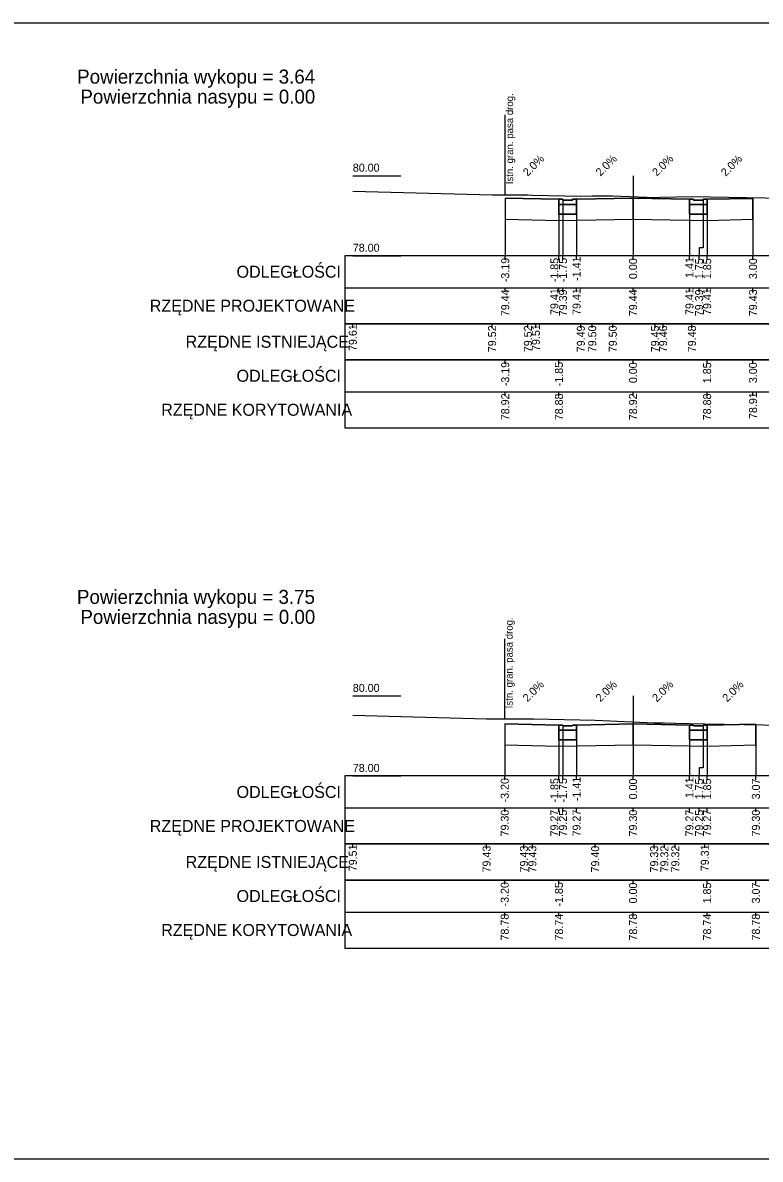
# Model space of a CAD drawing. Extents: x 7492871 to 7493499, y 5802964 to 5802992.
# Drawn here: x 7492955.98 to 7492974.4, y 5802963.88 to 5802992.28 of the extents above; entities that cross this region are included whole.
import ezdxf

# ---------------------------------------------------------------- set-up
doc = ezdxf.new("R2010")
doc.units = 0
for name, color, linetype in [('_wydruk', 7, 'Continuous'), ('d_pop_nasyp_opis', 7, 'Continuous'), ('d_pop_wykop_opis', 7, 'Continuous'), ('opisy_ramki_pop', 7, 'Continuous'), ('pop_comp_kostka', 7, 'Continuous'), ('pop_comp_lawa', 7, 'Continuous'), ('pop_comp_scieralna', 7, 'Continuous'), ('pop_granica_istn', 7, 'Continuous'), ('pop_opis', 7, 'Continuous'), ('pop_os', 7, 'Continuous'), ('pop_teren', 7, 'Continuous')]:
    doc.layers.add(name, color=color, linetype=linetype)

msp = doc.modelspace()

# ---------------------------------------------------------------- linework, layer by layer
for points in [[(7492968.028, 5802987.894), (7492969.37, 5802987.868), (7492969.47, 5802987.868), (7492969.471, 5802987.848), (7492969.71, 5802987.848), (7492969.711, 5802987.868), (7492969.811, 5802987.868), (7492971.221, 5802987.896), (7492972.631, 5802987.868), (7492972.731, 5802987.868), (7492972.732, 5802987.848), (7492972.971, 5802987.848), (7492972.972, 5802987.868), (7492973.072, 5802987.868), (7492974.218, 5802987.891)], [(7492968.016, 5802974.758), (7492969.37, 5802974.73), (7492969.47, 5802974.73), (7492969.471, 5802974.71), (7492969.71, 5802974.71), (7492969.711, 5802974.73), (7492969.811, 5802974.73), (7492971.221, 5802974.759), (7492972.631, 5802974.73), (7492972.731, 5802974.73), (7492972.732, 5802974.71), (7492972.971, 5802974.71), (7492972.972, 5802974.73), (7492973.072, 5802974.73), (7492974.29, 5802974.755)]]:
    msp.add_lwpolyline(points)
at = {"layer": '_wydruk'}
msp.add_lwpolyline([(7492871.369, 5802992.281), (7493499.283, 5802992.281), (7493499.283, 5802963.881), (7492871.369, 5802963.881)], close=True, dxfattribs=at)
at = {"layer": 'opisy_ramki_pop'}
for points in [[(7492968.028, 5802987.374), (7492968.028, 5802986.659), (7492968.028, 5802986.659), (7492968.028, 5802986.459)], [(7492969.37, 5802987.339), (7492969.37, 5802986.659), (7492969.37, 5802986.659), (7492969.37, 5802986.459)], [(7492971.221, 5802987.376), (7492971.221, 5802986.659), (7492971.221, 5802986.659), (7492971.221, 5802986.459)], [(7492973.072, 5802987.339), (7492973.072, 5802986.659), (7492973.072, 5802986.659), (7492973.072, 5802986.459)], [(7492974.218, 5802987.37), (7492974.218, 5802986.659), (7492974.218, 5802986.659), (7492974.218, 5802986.459)], [(7492968.016, 5802974.237), (7492968.016, 5802973.659), (7492968.016, 5802973.659), (7492968.016, 5802973.459)], [(7492969.37, 5802974.202), (7492969.37, 5802973.659), (7492969.37, 5802973.659), (7492969.37, 5802973.459)], [(7492971.221, 5802974.239), (7492971.221, 5802973.659), (7492971.221, 5802973.659), (7492971.221, 5802973.459)], [(7492973.072, 5802974.202), (7492973.072, 5802973.659), (7492973.072, 5802973.659), (7492973.072, 5802973.459)], [(7492974.29, 5802974.235), (7492974.29, 5802973.659), (7492974.29, 5802973.659), (7492974.29, 5802973.459)]]:
    msp.add_lwpolyline(points, dxfattribs=at)
at = {"layer": 'pop_comp_kostka'}
for p, q in [((7492969.47, 5802987.868), (7492969.37, 5802987.868)), ((7492969.37, 5802987.868), (7492969.37, 5802987.738)), ((7492969.37, 5802987.738), (7492969.811, 5802987.738)), ((7492969.471, 5802987.848), (7492969.47, 5802987.868)), ((7492969.71, 5802987.848), (7492969.471, 5802987.848)), ((7492969.711, 5802987.868), (7492969.71, 5802987.848)), ((7492969.811, 5802987.868), (7492969.711, 5802987.868)), ((7492969.811, 5802987.738), (7492969.811, 5802987.868)), ((7492972.731, 5802987.868), (7492972.631, 5802987.868)), ((7492972.631, 5802987.868), (7492972.631, 5802987.738)), ((7492972.631, 5802987.738), (7492973.072, 5802987.738)), ((7492972.732, 5802987.848), (7492972.731, 5802987.868)), ((7492972.971, 5802987.848), (7492972.732, 5802987.848)), ((7492972.972, 5802987.868), (7492972.971, 5802987.848)), ((7492973.072, 5802987.868), (7492972.972, 5802987.868)), ((7492973.072, 5802987.738), (7492973.072, 5802987.868)), ((7492969.47, 5802974.73), (7492969.37, 5802974.73)), ((7492969.37, 5802974.73), (7492969.37, 5802974.6)), ((7492969.37, 5802974.6), (7492969.811, 5802974.6)), ((7492969.471, 5802974.71), (7492969.47, 5802974.73)), ((7492969.71, 5802974.71), (7492969.471, 5802974.71)), ((7492969.711, 5802974.73), (7492969.71, 5802974.71)), ((7492969.811, 5802974.73), (7492969.711, 5802974.73)), ((7492969.811, 5802974.6), (7492969.811, 5802974.73)), ((7492972.731, 5802974.73), (7492972.631, 5802974.73)), ((7492972.631, 5802974.73), (7492972.631, 5802974.6)), ((7492972.631, 5802974.6), (7492973.072, 5802974.6)), ((7492972.732, 5802974.71), (7492972.731, 5802974.73)), ((7492972.971, 5802974.71), (7492972.732, 5802974.71)), ((7492972.972, 5802974.73), (7492972.971, 5802974.71)), ((7492973.072, 5802974.73), (7492972.972, 5802974.73)), ((7492973.072, 5802974.6), (7492973.072, 5802974.73))]:
    msp.add_line(p, q, dxfattribs=at)
at = {"layer": 'pop_comp_lawa'}
for p, q in [((7492969.811, 5802987.738), (7492969.37, 5802987.738)), ((7492969.37, 5802987.738), (7492969.37, 5802987.497)), ((7492969.811, 5802987.497), (7492969.811, 5802987.738)), ((7492973.072, 5802987.738), (7492972.631, 5802987.738)), ((7492972.631, 5802987.738), (7492972.631, 5802987.497)), ((7492973.072, 5802987.497), (7492973.072, 5802987.738)), ((7492969.37, 5802987.497), (7492969.811, 5802987.497)), ((7492972.631, 5802987.497), (7492973.072, 5802987.497)), ((7492969.811, 5802974.6), (7492969.37, 5802974.6)), ((7492969.37, 5802974.6), (7492969.37, 5802974.36)), ((7492969.811, 5802974.36), (7492969.811, 5802974.6)), ((7492973.072, 5802974.6), (7492972.631, 5802974.6)), ((7492972.631, 5802974.6), (7492972.631, 5802974.36)), ((7492973.072, 5802974.36), (7492973.072, 5802974.6)), ((7492969.37, 5802974.36), (7492969.811, 5802974.36)), ((7492972.631, 5802974.36), (7492973.072, 5802974.36))]:
    msp.add_line(p, q, dxfattribs=at)
at = {"layer": 'pop_comp_scieralna'}
for p, q in [((7492969.37, 5802987.868), (7492968.028, 5802987.894)), ((7492968.028, 5802987.894), (7492968.028, 5802987.374)), ((7492969.37, 5802987.497), (7492969.37, 5802987.868)), ((7492971.221, 5802987.896), (7492969.811, 5802987.868)), ((7492969.811, 5802987.868), (7492969.811, 5802987.497)), ((7492971.221, 5802987.376), (7492971.221, 5802987.896)), ((7492972.631, 5802987.868), (7492971.221, 5802987.896)), ((7492971.221, 5802987.896), (7492971.221, 5802987.376)), ((7492972.631, 5802987.497), (7492972.631, 5802987.868)), ((7492974.218, 5802987.891), (7492973.072, 5802987.868)), ((7492973.072, 5802987.868), (7492973.072, 5802987.497)), ((7492974.218, 5802987.37), (7492974.218, 5802987.891)), ((7492968.028, 5802987.374), (7492969.37, 5802987.339)), ((7492969.811, 5802987.497), (7492969.37, 5802987.497)), ((7492969.37, 5802987.339), (7492971.221, 5802987.376)), ((7492971.221, 5802987.376), (7492973.072, 5802987.339)), ((7492973.072, 5802987.497), (7492972.631, 5802987.497)), ((7492973.072, 5802987.339), (7492974.218, 5802987.37)), ((7492969.37, 5802974.73), (7492968.016, 5802974.758)), ((7492968.016, 5802974.758), (7492968.016, 5802974.237)), ((7492969.37, 5802974.36), (7492969.37, 5802974.73)), ((7492971.221, 5802974.759), (7492969.811, 5802974.73)), ((7492969.811, 5802974.73), (7492969.811, 5802974.36)), ((7492971.221, 5802974.239), (7492971.221, 5802974.759)), ((7492972.631, 5802974.73), (7492971.221, 5802974.759)), ((7492971.221, 5802974.759), (7492971.221, 5802974.239)), ((7492972.631, 5802974.36), (7492972.631, 5802974.73)), ((7492974.29, 5802974.755), (7492973.072, 5802974.73)), ((7492973.072, 5802974.73), (7492973.072, 5802974.36)), ((7492974.29, 5802974.235), (7492974.29, 5802974.755)), ((7492969.811, 5802974.36), (7492969.37, 5802974.36)), ((7492973.072, 5802974.36), (7492972.631, 5802974.36)), ((7492968.016, 5802974.237), (7492969.37, 5802974.202)), ((7492969.37, 5802974.202), (7492971.221, 5802974.239)), ((7492971.221, 5802974.239), (7492973.072, 5802974.202)), ((7492973.072, 5802974.202), (7492974.29, 5802974.235))]:
    msp.add_line(p, q, dxfattribs=at)
at = {"layer": 'pop_granica_istn'}
for p, q in [((7492968.028, 5802988.482), (7492968.028, 5802989.982)), ((7492968.028, 5802987.982), (7492968.028, 5802988.482)), ((7492968.016, 5802975.388), (7492968.016, 5802976.888)), ((7492968.016, 5802974.888), (7492968.016, 5802975.388))]:
    msp.add_line(p, q, dxfattribs=at)
at = {"layer": 'pop_opis'}
for p, q in [((7492964.221, 5802988.459), (7492965.421, 5802988.459)), ((7492964.021, 5802986.459), (7492964.021, 5802984.759)), ((7492964.021, 5802986.459), (7492964.021, 5802984.759)), ((7492964.021, 5802986.459), (7492964.021, 5802984.759)), ((7492964.021, 5802986.459), (7492964.021, 5802984.759)), ((7492964.221, 5802986.459), (7492965.421, 5802986.459)), ((7492968.028, 5802986.359), (7492968.028, 5802986.459)), ((7492969.37, 5802986.359), (7492969.37, 5802986.459)), ((7492969.471, 5802986.359), (7492969.471, 5802986.459)), ((7492969.811, 5802986.359), (7492969.811, 5802986.459)), ((7492971.221, 5802986.359), (7492971.221, 5802986.459)), ((7492972.631, 5802986.359), (7492972.631, 5802986.459)), ((7492972.872, 5802986.359), (7492972.872, 5802986.459)), ((7492973.072, 5802986.359), (7492973.072, 5802986.459)), ((7492974.218, 5802986.359), (7492974.218, 5802986.459)), ((7492964.021, 5802985.659), (7492978.421, 5802985.659)), ((7492964.021, 5802985.659), (7492978.421, 5802985.659)), ((7492964.021, 5802985.659), (7492978.421, 5802985.659)), ((7492964.021, 5802985.659), (7492978.421, 5802985.659)), ((7492968.028, 5802985.559), (7492968.028, 5802985.659)), ((7492969.37, 5802985.559), (7492969.37, 5802985.659)), ((7492969.471, 5802985.559), (7492969.471, 5802985.659)), ((7492969.811, 5802985.559), (7492969.811, 5802985.659)), ((7492971.221, 5802985.559), (7492971.221, 5802985.659)), ((7492972.631, 5802985.559), (7492972.631, 5802985.659)), ((7492972.872, 5802985.559), (7492972.872, 5802985.659)), ((7492973.072, 5802985.559), (7492973.072, 5802985.659)), ((7492974.218, 5802985.559), (7492974.218, 5802985.659)), ((7492964.021, 5802984.759), (7492964.021, 5802983.859)), ((7492964.221, 5802984.659), (7492964.221, 5802984.759)), ((7492967.7, 5802984.659), (7492967.7, 5802984.759)), ((7492968.594, 5802984.659), (7492968.594, 5802984.759)), ((7492968.794, 5802984.659), (7492968.794, 5802984.759)), ((7492969.917, 5802984.659), (7492969.917, 5802984.759)), ((7492970.203, 5802984.659), (7492970.203, 5802984.759)), ((7492970.715, 5802984.659), (7492970.715, 5802984.759)), ((7492971.771, 5802984.659), (7492971.771, 5802984.759)), ((7492971.971, 5802984.659), (7492971.971, 5802984.759)), ((7492972.692, 5802984.659), (7492972.692, 5802984.759)), ((7492964.021, 5802983.859), (7492964.021, 5802982.159)), ((7492968.028, 5802983.759), (7492968.028, 5802983.859)), ((7492969.37, 5802983.759), (7492969.37, 5802983.859)), ((7492971.221, 5802983.759), (7492971.221, 5802983.859)), ((7492973.072, 5802983.759), (7492973.072, 5802983.859)), ((7492974.218, 5802983.759), (7492974.218, 5802983.859)), ((7492964.021, 5802983.059), (7492978.421, 5802983.059)), ((7492968.028, 5802982.959), (7492968.028, 5802983.059)), ((7492969.37, 5802982.959), (7492969.37, 5802983.059)), ((7492971.221, 5802982.959), (7492971.221, 5802983.059)), ((7492973.072, 5802982.959), (7492973.072, 5802983.059)), ((7492974.218, 5802982.959), (7492974.218, 5802983.059)), ((7492964.221, 5802975.459), (7492965.421, 5802975.459)), ((7492964.021, 5802973.459), (7492964.021, 5802971.759)), ((7492964.021, 5802973.459), (7492964.021, 5802971.759)), ((7492964.021, 5802973.459), (7492964.021, 5802971.759)), ((7492964.021, 5802973.459), (7492964.021, 5802971.759)), ((7492964.221, 5802973.459), (7492965.421, 5802973.459)), ((7492968.016, 5802973.359), (7492968.016, 5802973.459)), ((7492969.37, 5802973.359), (7492969.37, 5802973.459)), ((7492969.471, 5802973.359), (7492969.471, 5802973.459)), ((7492969.811, 5802973.359), (7492969.811, 5802973.459)), ((7492971.221, 5802973.359), (7492971.221, 5802973.459)), ((7492972.631, 5802973.359), (7492972.631, 5802973.459)), ((7492972.872, 5802973.359), (7492972.872, 5802973.459)), ((7492973.072, 5802973.359), (7492973.072, 5802973.459)), ((7492974.29, 5802973.359), (7492974.29, 5802973.459)), ((7492964.021, 5802972.659), (7492978.421, 5802972.659)), ((7492964.021, 5802972.659), (7492978.421, 5802972.659)), ((7492964.021, 5802972.659), (7492978.421, 5802972.659)), ((7492964.021, 5802972.659), (7492978.421, 5802972.659)), ((7492968.016, 5802972.559), (7492968.016, 5802972.659)), ((7492969.37, 5802972.559), (7492969.37, 5802972.659)), ((7492969.471, 5802972.559), (7492969.471, 5802972.659)), ((7492969.811, 5802972.559), (7492969.811, 5802972.659)), ((7492971.221, 5802972.559), (7492971.221, 5802972.659)), ((7492972.631, 5802972.559), (7492972.631, 5802972.659)), ((7492972.872, 5802972.559), (7492972.872, 5802972.659)), ((7492973.072, 5802972.559), (7492973.072, 5802972.659)), ((7492974.29, 5802972.559), (7492974.29, 5802972.659)), ((7492964.021, 5802971.759), (7492964.021, 5802970.859)), ((7492964.221, 5802971.659), (7492964.221, 5802971.759)), ((7492967.563, 5802971.659), (7492967.563, 5802971.759)), ((7492968.496, 5802971.659), (7492968.496, 5802971.759)), ((7492968.706, 5802971.659), (7492968.706, 5802971.759)), ((7492970.275, 5802971.659), (7492970.275, 5802971.759)), ((7492971.749, 5802971.659), (7492971.749, 5802971.759)), ((7492972.004, 5802971.659), (7492972.004, 5802971.759)), ((7492972.277, 5802971.659), (7492972.277, 5802971.759)), ((7492973.013, 5802971.659), (7492973.013, 5802971.759)), ((7492964.021, 5802970.859), (7492964.021, 5802969.159)), ((7492968.016, 5802970.759), (7492968.016, 5802970.859)), ((7492969.37, 5802970.759), (7492969.37, 5802970.859)), ((7492971.221, 5802970.759), (7492971.221, 5802970.859)), ((7492973.072, 5802970.759), (7492973.072, 5802970.859)), ((7492974.29, 5802970.759), (7492974.29, 5802970.859)), ((7492964.021, 5802970.059), (7492978.421, 5802970.059)), ((7492968.016, 5802969.959), (7492968.016, 5802970.059)), ((7492969.37, 5802969.959), (7492969.37, 5802970.059)), ((7492971.221, 5802969.959), (7492971.221, 5802970.059)), ((7492973.072, 5802969.959), (7492973.072, 5802970.059)), ((7492974.29, 5802969.959), (7492974.29, 5802970.059))]:
    msp.add_line(p, q, dxfattribs=at)
for points in [[(7492968.028, 5802987.894), (7492968.028, 5802986.659), (7492968.028, 5802986.659), (7492968.028, 5802986.459)], [(7492969.37, 5802987.868), (7492969.37, 5802986.659), (7492969.37, 5802986.659), (7492969.37, 5802986.459)], [(7492969.471, 5802987.848), (7492969.471, 5802986.659), (7492969.471, 5802986.659), (7492969.471, 5802986.459)], [(7492969.811, 5802987.868), (7492969.811, 5802986.659), (7492969.811, 5802986.659), (7492969.811, 5802986.459)], [(7492971.221, 5802987.896), (7492971.221, 5802986.659), (7492971.221, 5802986.659), (7492971.221, 5802986.459)], [(7492972.631, 5802987.868), (7492972.631, 5802986.659), (7492972.631, 5802986.659), (7492972.631, 5802986.459)], [(7492972.971, 5802987.848), (7492972.971, 5802986.659), (7492972.872, 5802986.659), (7492972.872, 5802986.459)], [(7492973.072, 5802987.868), (7492973.072, 5802986.659), (7492973.072, 5802986.659), (7492973.072, 5802986.459)], [(7492974.218, 5802987.891), (7492974.218, 5802986.659), (7492974.218, 5802986.659), (7492974.218, 5802986.459)], [(7492968.016, 5802974.758), (7492968.016, 5802973.659), (7492968.016, 5802973.659), (7492968.016, 5802973.459)], [(7492969.37, 5802974.73), (7492969.37, 5802973.659), (7492969.37, 5802973.659), (7492969.37, 5802973.459)], [(7492969.471, 5802974.71), (7492969.471, 5802973.659), (7492969.471, 5802973.659), (7492969.471, 5802973.459)], [(7492969.811, 5802974.73), (7492969.811, 5802973.659), (7492969.811, 5802973.659), (7492969.811, 5802973.459)], [(7492971.221, 5802974.759), (7492971.221, 5802973.659), (7492971.221, 5802973.659), (7492971.221, 5802973.459)], [(7492972.631, 5802974.73), (7492972.631, 5802973.659), (7492972.631, 5802973.659), (7492972.631, 5802973.459)], [(7492972.971, 5802974.71), (7492972.971, 5802973.659), (7492972.872, 5802973.659), (7492972.872, 5802973.459)], [(7492973.072, 5802974.73), (7492973.072, 5802973.659), (7492973.072, 5802973.659), (7492973.072, 5802973.459)], [(7492974.29, 5802974.755), (7492974.29, 5802973.659), (7492974.29, 5802973.659), (7492974.29, 5802973.459)]]:
    msp.add_lwpolyline(points, dxfattribs=at)
for points in [[(7492964.021, 5802986.459), (7492964.021, 5802984.759), (7492978.421, 5802984.759), (7492978.421, 5802986.459)], [(7492964.021, 5802986.459), (7492964.021, 5802984.759), (7492978.421, 5802984.759), (7492978.421, 5802986.459)], [(7492964.021, 5802986.459), (7492964.021, 5802984.759), (7492978.421, 5802984.759), (7492978.421, 5802986.459)], [(7492964.021, 5802986.459), (7492964.021, 5802984.759), (7492978.421, 5802984.759), (7492978.421, 5802986.459)], [(7492964.021, 5802984.759), (7492964.021, 5802983.859), (7492978.421, 5802983.859), (7492978.421, 5802984.759)], [(7492964.021, 5802983.859), (7492964.021, 5802982.159), (7492978.421, 5802982.159), (7492978.421, 5802983.859)], [(7492964.021, 5802973.459), (7492964.021, 5802971.759), (7492978.421, 5802971.759), (7492978.421, 5802973.459)], [(7492964.021, 5802973.459), (7492964.021, 5802971.759), (7492978.421, 5802971.759), (7492978.421, 5802973.459)], [(7492964.021, 5802973.459), (7492964.021, 5802971.759), (7492978.421, 5802971.759), (7492978.421, 5802973.459)], [(7492964.021, 5802973.459), (7492964.021, 5802971.759), (7492978.421, 5802971.759), (7492978.421, 5802973.459)], [(7492964.021, 5802971.759), (7492964.021, 5802970.859), (7492978.421, 5802970.859), (7492978.421, 5802971.759)], [(7492964.021, 5802970.859), (7492964.021, 5802969.159), (7492978.421, 5802969.159), (7492978.421, 5802970.859)]]:
    msp.add_lwpolyline(points, close=True, dxfattribs=at)
at = {"layer": 'pop_os'}
for p, q in [((7492971.221, 5802988.459), (7492971.221, 5802986.459)), ((7492971.221, 5802975.459), (7492971.221, 5802973.459))]:
    msp.add_line(p, q, dxfattribs=at)
at = {"layer": 'pop_teren'}
for points in [[(7492964.221, 5802988.072), (7492967.7, 5802987.983), (7492968.594, 5802987.983), (7492968.708, 5802987.972), (7492969.917, 5802987.949), (7492970.203, 5802987.954), (7492970.715, 5802987.956), (7492971.771, 5802987.91), (7492971.895, 5802987.919), (7492972.692, 5802987.942), (7492976.366, 5802987.876), (7492978.221, 5802987.859)], [(7492964.221, 5802974.974), (7492967.563, 5802974.888), (7492968.496, 5802974.888), (7492968.706, 5802974.888), (7492968.736, 5802974.887), (7492970.275, 5802974.854), (7492971.749, 5802974.79), (7492972.004, 5802974.783), (7492972.277, 5802974.776), (7492973.013, 5802974.765), (7492977.401, 5802974.685), (7492978.221, 5802974.678)]]:
    msp.add_lwpolyline(points, dxfattribs=at)

# ---------------------------------------------------------------- texts
at = {"layer": 'd_pop_nasyp_opis'}
for p in [(7492957.416, 5802990.259), (7492957.416, 5802977.259)]:
    msp.add_text('Powierzchnia nasypu = 0.00', height=0.35, dxfattribs=at).set_placement(p)
at = {"layer": 'd_pop_wykop_opis'}
for s, p in [('Powierzchnia wykopu = 3.64', (7492957.335, 5802990.759)), ('Powierzchnia wykopu = 3.75', (7492957.33, 5802977.759))]:
    msp.add_text(s, height=0.35, dxfattribs=at).set_placement(p)
at = {"layer": 'pop_granica_istn'}
for p in [(7492968.226, 5802988.244), (7492968.214, 5802975.149)]:
    msp.add_text('Istn. gran. pasa drog.', height=0.18, rotation=90, dxfattribs=at).set_placement(p)
at = {"layer": 'pop_opis'}
for s, height, p in [('80.00', 0.2, (7492964.221, 5802988.559)), ('78.00', 0.2, (7492964.221, 5802986.559)), ('ODLEGŁOŚCI', 0.3, (7492961.317, 5802985.909)), ('ODLEGŁOŚCI', 0.3, (7492961.317, 5802985.909)), ('ODLEGŁOŚCI', 0.3, (7492961.317, 5802985.909)), ('ODLEGŁOŚCI', 0.3, (7492961.317, 5802985.909)), ('RZĘDNE PROJEKTOWANE', 0.3, (7492959.149, 5802985.059)), ('RZĘDNE PROJEKTOWANE', 0.3, (7492959.149, 5802985.059)), ('RZĘDNE PROJEKTOWANE', 0.3, (7492959.149, 5802985.059)), ('RZĘDNE PROJEKTOWANE', 0.3, (7492959.149, 5802985.059)), ('RZĘDNE ISTNIEJĄCE', 0.3, (7492960.045, 5802984.159)), ('ODLEGŁOŚCI', 0.3, (7492961.317, 5802983.309)), ('RZĘDNE KORYTOWANIA', 0.3, (7492959.435, 5802982.459)), ('80.00', 0.2, (7492964.221, 5802975.559)), ('78.00', 0.2, (7492964.221, 5802973.559)), ('ODLEGŁOŚCI', 0.3, (7492961.317, 5802972.909)), ('ODLEGŁOŚCI', 0.3, (7492961.317, 5802972.909)), ('ODLEGŁOŚCI', 0.3, (7492961.317, 5802972.909)), ('ODLEGŁOŚCI', 0.3, (7492961.317, 5802972.909)), ('RZĘDNE PROJEKTOWANE', 0.3, (7492959.149, 5802972.059)), ('RZĘDNE PROJEKTOWANE', 0.3, (7492959.149, 5802972.059)), ('RZĘDNE PROJEKTOWANE', 0.3, (7492959.149, 5802972.059)), ('RZĘDNE PROJEKTOWANE', 0.3, (7492959.149, 5802972.059)), ('RZĘDNE ISTNIEJĄCE', 0.3, (7492960.045, 5802971.159)), ('ODLEGŁOŚCI', 0.3, (7492961.317, 5802970.309)), ('RZĘDNE KORYTOWANIA', 0.3, (7492959.435, 5802969.459))]:
    msp.add_text(s, height=height, dxfattribs=at).set_placement(p)
for s, rotation, p in [('2.0%', 45, (7492968.59, 5802988.431)), ('2.0%', 45, (7492970.407, 5802988.432)), ('2.0%', 45, (7492971.817, 5802988.432)), ('2.0%', 45, (7492973.536, 5802988.429)), ('-3.19', 90, (7492968.128, 5802985.797)), ('-1.85', 90, (7492969.356, 5802985.796)), ('-1.75', 90, (7492969.571, 5802985.796)), ('-1.41', 90, (7492969.911, 5802985.829)), ('0.00', 90, (7492971.321, 5802985.874)), ('1.41', 90, (7492972.731, 5802985.905)), ('1.75', 90, (7492972.972, 5802985.873)), ('1.85', 90, (7492973.172, 5802985.873)), ('3.00', 90, (7492974.318, 5802985.874)), ('79.41', 90, (7492969.356, 5802984.978)), ('79.41', 90, (7492969.911, 5802984.978)), ('79.41', 90, (7492972.731, 5802984.978)), ('79.41', 90, (7492973.172, 5802984.978)), ('79.44', 90, (7492968.128, 5802984.947)), ('79.39', 90, (7492969.571, 5802984.946)), ('79.44', 90, (7492971.321, 5802984.947)), ('79.39', 90, (7492972.972, 5802984.946)), ('79.43', 90, (7492974.318, 5802984.947)), ('79.61', 90, (7492964.321, 5802984.078)), ('79.52', 90, (7492967.8, 5802984.048)), ('79.52', 90, (7492968.694, 5802984.048)), ('79.51', 90, (7492968.894, 5802984.078)), ('79.49', 90, (7492970.017, 5802984.046)), ('79.50', 90, (7492970.303, 5802984.047)), ('79.50', 90, (7492970.815, 5802984.047)), ('79.45', 90, (7492971.871, 5802984.045)), ('79.46', 90, (7492972.071, 5802984.047)), ('79.48', 90, (7492972.792, 5802984.046)), ('-3.19', 90, (7492968.128, 5802983.197)), ('-1.85', 90, (7492969.47, 5802983.196)), ('0.00', 90, (7492971.321, 5802983.274)), ('1.85', 90, (7492973.172, 5802983.273)), ('3.00', 90, (7492974.318, 5802983.274)), ('78.92', 90, (7492968.128, 5802982.348)), ('78.88', 90, (7492969.47, 5802982.346)), ('78.92', 90, (7492971.321, 5802982.348)), ('78.88', 90, (7492973.172, 5802982.346)), ('78.91', 90, (7492974.318, 5802982.378)), ('2.0%', 45, (7492968.584, 5802975.294)), ('2.0%', 45, (7492970.407, 5802975.294)), ('2.0%', 45, (7492971.817, 5802975.294)), ('2.0%', 45, (7492973.572, 5802975.293)), ('-1.41', 90, (7492969.911, 5802972.829)), ('-3.20', 90, (7492968.116, 5802972.798)), ('-1.85', 90, (7492969.356, 5802972.796)), ('-1.75', 90, (7492969.571, 5802972.796)), ('0.00', 90, (7492971.321, 5802972.874)), ('1.41', 90, (7492972.731, 5802972.905)), ('1.75', 90, (7492972.972, 5802972.873)), ('1.85', 90, (7492973.172, 5802972.873)), ('3.07', 90, (7492974.39, 5802972.874)), ('79.30', 90, (7492968.116, 5802971.947)), ('79.27', 90, (7492969.356, 5802971.947)), ('79.25', 90, (7492969.571, 5802971.945)), ('79.27', 90, (7492969.911, 5802971.947)), ('79.30', 90, (7492971.321, 5802971.947)), ('79.27', 90, (7492972.731, 5802971.947)), ('79.25', 90, (7492972.972, 5802971.945)), ('79.27', 90, (7492973.172, 5802971.947)), ('79.30', 90, (7492974.39, 5802971.947)), ('79.51', 90, (7492964.321, 5802971.078)), ('79.31', 90, (7492973.113, 5802971.078)), ('79.43', 90, (7492967.663, 5802971.047)), ('79.43', 90, (7492968.596, 5802971.047)), ('79.43', 90, (7492968.806, 5802971.047)), ('79.40', 90, (7492970.375, 5802971.047)), ('79.33', 90, (7492971.849, 5802971.047)), ('79.32', 90, (7492972.104, 5802971.048)), ('79.32', 90, (7492972.377, 5802971.048)), ('-3.20', 90, (7492968.116, 5802970.198)), ('-1.85', 90, (7492969.47, 5802970.196)), ('0.00', 90, (7492971.321, 5802970.274)), ('1.85', 90, (7492973.172, 5802970.273)), ('3.07', 90, (7492974.39, 5802970.274)), ('78.78', 90, (7492968.116, 5802969.346)), ('78.74', 90, (7492969.47, 5802969.347)), ('78.78', 90, (7492971.321, 5802969.346)), ('78.74', 90, (7492973.172, 5802969.347)), ('78.78', 90, (7492974.39, 5802969.346))]:
    msp.add_text(s, height=0.2, rotation=rotation, dxfattribs=at).set_placement(p)

doc.saveas('drawing.dxf')
